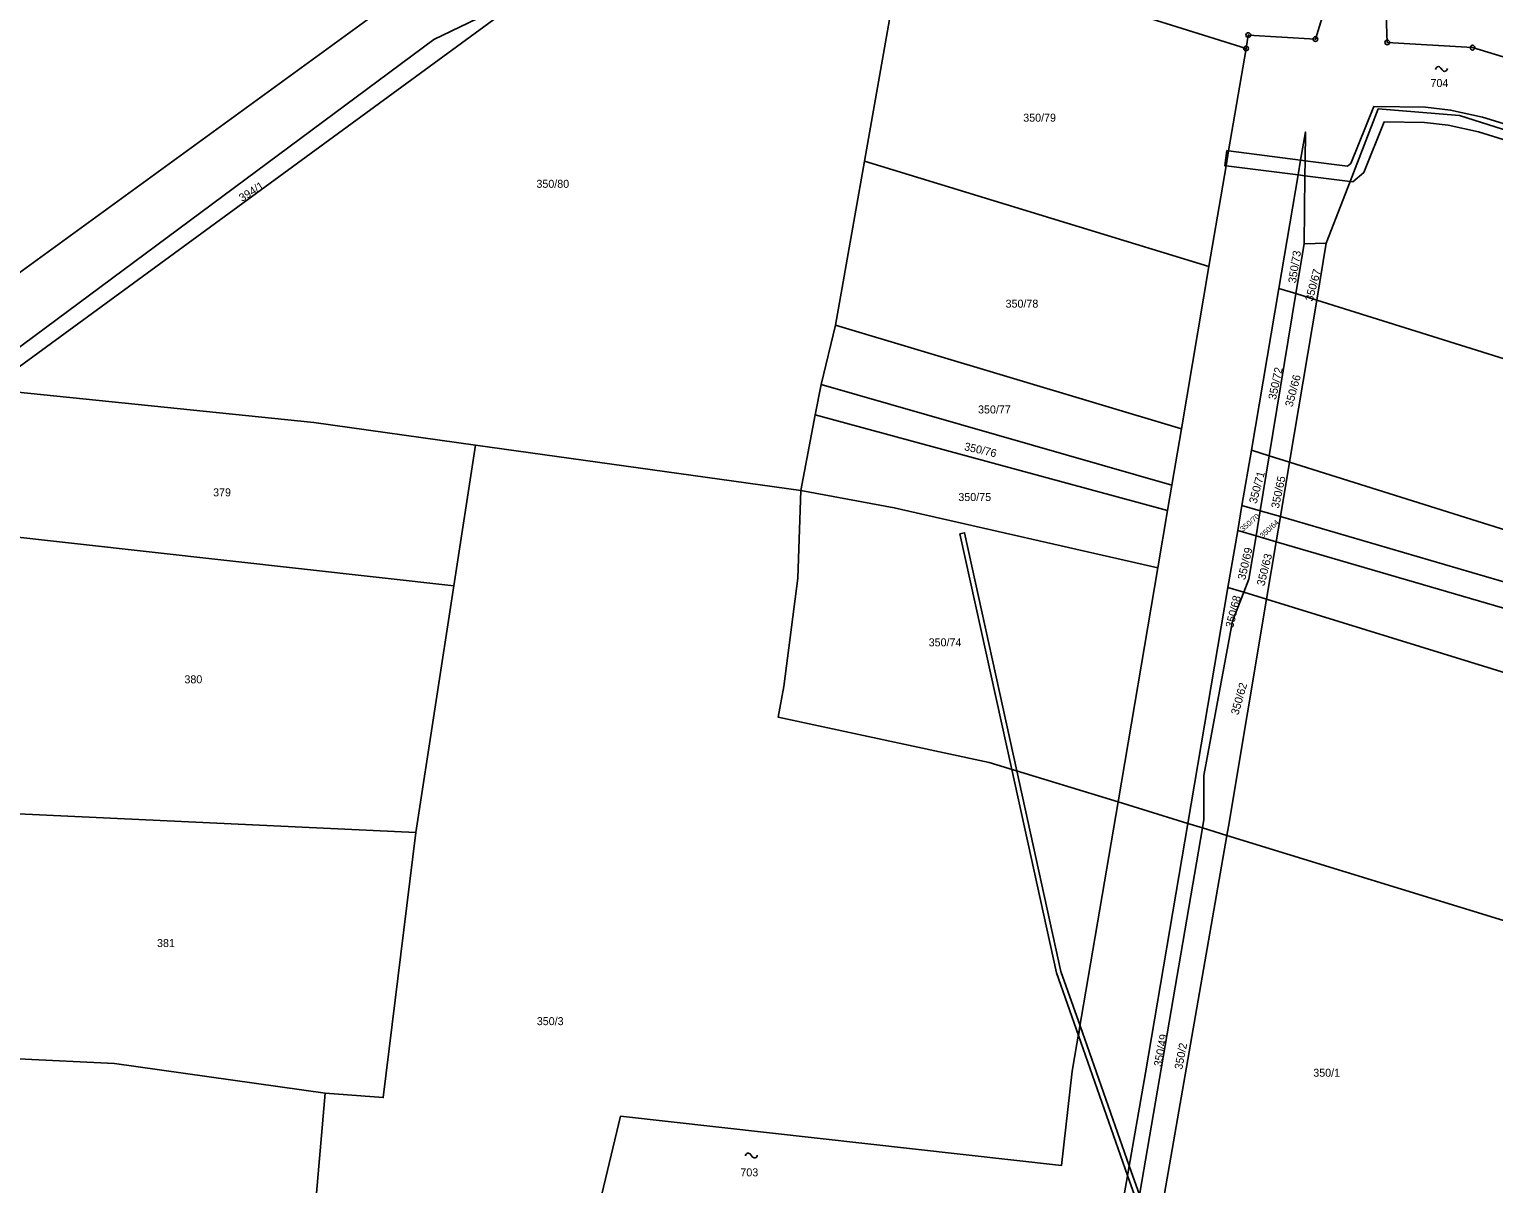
# Model space of a CAD drawing. Extents: x -758582 to -751794, y -998770 to -994350.
# Drawn here: x -756359.8 to -756048.6, y -995042.4 to -994797.3 of the extents above; entities that cross this region are included whole.
import ezdxf

# ---------------------------------------------------------------- set-up
doc = ezdxf.new("R2010")
doc.units = 0
for name, color, linetype in [('Hranice parcel', 7, 'Continuous'), ('Parcelní čísla', 7, 'Continuous'), ('Věcná břemena k části', 7, 'Continuous'), ('Značky bodu BP', 7, 'Continuous'), ('Značky budov', 7, 'Continuous')]:
    doc.layers.add(name, color=color, linetype=linetype)

msp = doc.modelspace()

# ---------------------------------------------------------------- linework, layer by layer
at = {"layer": 'Hranice parcel'}
for p, q in [((-756086.52, -994799.34), (-756077.42, -994769.66)), ((-756072.33, -994770.65), (-756071.25, -994800.04)), ((-756174.03, -994778.41), (-756182.33, -994825.28)), ((-756174.03, -994778.41), (-756101.26, -994801.32)), ((-756368.47, -994873.7), (-756253.61, -994789.69)), ((-756281.77, -994790.62), (-756367.18, -994852.8)), ((-756101.26, -994801.32), (-756100.77, -994798.48)), ((-756100.77, -994798.48), (-756086.52, -994799.34)), ((-756182.33, -994825.28), (-756188.49, -994860.1)), ((-756109.13, -994847.66), (-756182.33, -994825.28)), ((-756088.93, -994842.79), (-756090.67, -994853.4)), ((-756088.93, -994842.79), (-756084.22, -994842.66)), ((-756084.22, -994842.66), (-756086.25, -994854.78)), ((-756109.13, -994847.66), (-756114.98, -994882.08)), ((-756100.13, -994886.64), (-756094.29, -994852.27)), ((-756090.67, -994853.4), (-756094.29, -994852.27)), ((-756090.67, -994853.4), (-756096.32, -994887.83)), ((-756086.25, -994854.78), (-756092.02, -994889.17)), ((-756086.25, -994854.78), (-756090.67, -994853.4)), ((-755905.48, -994911.3), (-756086.25, -994854.78)), ((-756188.49, -994860.1), (-756191.49, -994872.7)), ((-756114.98, -994882.08), (-756188.49, -994860.1)), ((-756191.49, -994872.7), (-756192.81, -994879.15)), ((-756117.01, -994894.05), (-756191.49, -994872.7)), ((-756192.81, -994879.15), (-756195.86, -994895.23)), ((-756117.93, -994899.48), (-756192.81, -994879.15)), ((-756114.98, -994882.08), (-756117.01, -994894.05)), ((-756264.95, -994885.59), (-756269.57, -994915.48)), ((-756195.86, -994895.23), (-756264.95, -994885.59)), ((-756102.12, -994898.36), (-756100.13, -994886.64)), ((-756096.32, -994887.83), (-756100.13, -994886.64)), ((-756096.32, -994887.83), (-756098.24, -994899.49)), ((-756092.02, -994889.17), (-756096.32, -994887.83)), ((-756092.02, -994889.17), (-756093.96, -994900.74)), ((-756117.01, -994894.05), (-756117.93, -994899.48)), ((-756117.93, -994899.48), (-756120, -994911.65)), ((-756103.03, -994903.71), (-756102.12, -994898.36)), ((-756098.24, -994899.49), (-756102.12, -994898.36)), ((-756098.24, -994899.49), (-756099.12, -994904.85)), ((-756093.96, -994900.74), (-756098.24, -994899.49)), ((-756093.96, -994900.74), (-756094.86, -994906.09)), ((-755913.68, -994953.37), (-756093.96, -994900.74)), ((-756373.06, -994903.94), (-756269.57, -994915.48)), ((-756105.09, -994915.79), (-756103.03, -994903.71)), ((-756099.12, -994904.85), (-756103.03, -994903.71)), ((-756094.86, -994906.09), (-756099.12, -994904.85)), ((-756094.86, -994906.09), (-756096.9, -994918.28)), ((-755914.5, -994958.67), (-756094.86, -994906.09)), ((-756120, -994911.65), (-756128.44, -994961.35)), ((-756269.57, -994915.48), (-756277.66, -994967.84)), ((-756113.6, -994965.91), (-756105.09, -994915.79)), ((-756101.73, -994916.81), (-756105.09, -994915.79)), ((-756101.73, -994916.81), (-756104.15, -994922.93)), ((-756096.9, -994918.28), (-756101.73, -994916.81)), ((-756128.44, -994961.35), (-756113.6, -994965.91)), ((-756381.87, -994962.95), (-756277.66, -994967.84)), ((-756110.5, -994966.86), (-756125.92, -995056.48)), ((-756110.5, -994966.86), (-756113.6, -994965.91)), ((-756110.19, -994965.07), (-756110.5, -994966.86)), ((-756105.33, -994968.45), (-756110.5, -994966.86)), ((-756105.33, -994968.45), (-756120.81, -995057.12)), ((-756042.86, -994987.64), (-756105.33, -994968.45))]:
    msp.add_line(p, q, dxfattribs=at)
for points in [[(-756253.61, -994789.69), (-756273.78, -994799.42), (-756368.18, -994869.46)], [(-756071.25, -994800.04), (-756053.14, -994801.16), (-755892.22, -994850.06), (-755894.52, -994857.69)], [(-756101.26, -994801.32), (-756104.95, -994823.07), (-756105.49, -994826.28), (-756109.13, -994847.66)], [(-756084.22, -994842.66), (-756079.17, -994829.59), (-756073.22, -994814.18)], [(-756073.22, -994814.18), (-756055.93, -994815.59), (-755897.05, -994866.03)], [(-756094.29, -994852.27), (-756090.2, -994828.2), (-756089.67, -994825.06), (-756088.65, -994819.06), (-756088.72, -994825.18), (-756088.76, -994828.38), (-756088.93, -994842.79)], [(-756368.47, -994873.7), (-756299.29, -994880.74), (-756264.95, -994885.59)], [(-755912.3, -994944.36), (-756023.52, -994910.68), (-756092.02, -994889.17)], [(-756128.44, -994961.35), (-756155.83, -994952.96), (-756200.68, -994943.33), (-756199.43, -994936.86), (-756196.48, -994913.85), (-756195.86, -994895.23)], [(-756120, -994911.65), (-756175.98, -994898.88), (-756195.86, -994895.23)], [(-756099.12, -994904.85), (-756100.63, -994914.03), (-756101.73, -994916.81)], [(-756096.9, -994918.28), (-756105, -994966.58), (-756105.33, -994968.45)], [(-755916.67, -994973.02), (-755989.55, -994951.4), (-756096.9, -994918.28)], [(-756104.15, -994922.93), (-756110.2, -994955.75), (-756110.19, -994965.07)], [(-756234.17, -995028.1), (-756140.46, -995038.54), (-756138.16, -995018.51), (-756128.44, -994961.35)], [(-756277.66, -994967.84), (-756284.57, -995024.14), (-756296.89, -995023.16)], [(-756113.6, -994965.91), (-756122.6, -995018.87), (-756129.13, -995056.13)], [(-756362.08, -995015.86), (-756341.64, -995016.88), (-756296.89, -995023.16)], [(-756296.89, -995023.16), (-756301.28, -995073.82), (-756306.95, -995125.13), (-756317.06, -995199.97), (-756321.88, -995219.72)], [(-756295.79, -995218.6), (-756267.28, -995166.44), (-756234.17, -995028.1)]]:
    msp.add_lwpolyline(points, dxfattribs=at)
at = {"layer": 'Věcná břemena k části'}
for points in [[(-756088.72, -994825.18), (-756088.76, -994828.38), (-756079.17, -994829.59), (-756073.22, -994814.18), (-756055.93, -994815.59), (-755897.05, -994866.03), (-755893.83, -994867.05), (-755893.03, -994864.4), (-755896.29, -994863.5), (-755899.3, -994862.67), (-755925.08, -994855.31), (-755970.88, -994840.97), (-756016.69, -994826.72), (-756039.51, -994819.46), (-756051.05, -994815.89), (-756057.79, -994814.43), (-756063.16, -994813.8), (-756074.11, -994813.66), (-756078.96, -994825.73), (-756079.69, -994826.35)], [(-755893.95, -994867.51), (-755893.83, -994867.05), (-755897.05, -994866.03), (-756055.93, -994815.59), (-756073.22, -994814.18), (-756079.17, -994829.59), (-756078.6, -994829.66), (-756076.25, -994827.69), (-756071.94, -994816.93), (-756063.37, -994817.04), (-756058.32, -994817.63), (-756051.89, -994819.03), (-756040.48, -994822.55), (-756017.66, -994829.81), (-755971.85, -994844.06), (-755926.01, -994858.42), (-755900.18, -994865.79)], [(-756105.37, -994823.02), (-756105.78, -994826.24), (-756105.49, -994826.28), (-756104.95, -994823.07)], [(-756104.95, -994823.07), (-756105.49, -994826.28), (-756090.2, -994828.2), (-756089.67, -994825.06)], [(-756089.67, -994825.06), (-756090.2, -994828.2), (-756088.76, -994828.38), (-756088.72, -994825.18)], [(-756149.94, -994954.76), (-756161.06, -994904.19), (-756162.04, -994904.41), (-756151.04, -994954.43)], [(-756151.04, -994954.43), (-756141.54, -994997.65), (-756136.87, -995010.93), (-756136.53, -995008.9), (-756140.58, -994997.37), (-756149.94, -994954.76)], [(-756136.53, -995008.9), (-756136.87, -995010.93), (-756126.42, -995040.65), (-756126.07, -995038.64)], [(-756126.42, -995040.65), (-756124.26, -995046.8), (-756120.81, -995057.12), (-756119.5, -995057.3), (-756120.4, -995054.76), (-756123.91, -995044.78), (-756126.07, -995038.64)]]:
    msp.add_lwpolyline(points, close=True, dxfattribs=at)
at = {"layer": 'Značky bodu BP'}
for centre, radius in [((-756100.77, -994798.48), 0.5), ((-756100.77, -994798.48), 0.0303), ((-756086.52, -994799.34), 0.5), ((-756086.52, -994799.34), 0.0303), ((-756071.25, -994800.04), 0.5), ((-756071.25, -994800.04), 0.0303), ((-756101.26, -994801.32), 0.5), ((-756101.26, -994801.32), 0.0303), ((-756053.14, -994801.16), 0.5), ((-756053.14, -994801.16), 0.0303)]:
    msp.add_circle(centre, radius, dxfattribs=at)
at = {"layer": 'Značky budov'}
for p, q in [((-756059.89, -994805.49), (-756059.59, -994805.89)), ((-756206.5, -995036.22), (-756206.2, -995036.62))]:
    msp.add_line(p, q, dxfattribs=at)
for centre, start, end in [((-756060.4, -994805.78), 29.2914, 181.2189), ((-756059.08, -994805.6), 209.2914, 1.2189), ((-756207.01, -995036.51), 29.2914, 181.2189), ((-756205.69, -995036.33), 209.2914, 1.2189)]:
    msp.add_arc(centre, 0.588, start, end, dxfattribs=at)

# ---------------------------------------------------------------- texts
at = {"layer": 'Parcelní čísla'}
for s, p in [('704', (-756062.07, -994809.52)), ('350/79', (-756148.59, -994816.88)), ('350/80', (-756252.01, -994830.92)), ('350/78', (-756152.34, -994856.37)), ('350/77', (-756158.19, -994878.84)), ('379', (-756320.7, -994896.45)), ('350/75', (-756162.37, -994897.44)), ('350/74', (-756168.68, -994928.3)), ('380', (-756326.79, -994936.15)), ('381', (-756332.61, -994992.16)), ('350/3', (-756251.93, -995008.74)), ('350/1', (-756086.97, -995019.7)), ('703', (-756208.68, -995040.85))]:
    msp.add_text(s, height=1.7, dxfattribs=at).set_placement(p)
for s, height, rotation, p in [('394/1', 1.7, 32, (-756314.54, -994833.95)), ('350/73', 1.7, 81, (-756090.66, -994851.27)), ('350/67', 1.7, 75, (-756087.11, -994855.16)), ('350/72', 1.7, 78, (-756094.91, -994876.04)), ('350/66', 1.7, 75, (-756091.39, -994877.58)), ('350/76', 1.7, 347, (-756161.25, -994886.61)), ('350/71', 1.7, 75, (-756099.03, -994898.11)), ('350/65', 1.7, 78, (-756094.3, -994899.13)), ('350/70', 1.14, 41, (-756101.9, -994904.01)), ('350/64', 1.14, 43, (-756097.68, -994905.41)), ('350/69', 1.7, 77, (-756101.43, -994914.3)), ('350/63', 1.7, 76, (-756097.37, -994915.58)), ('350/68', 1.7, 76, (-756104.01, -994924.5)), ('350/62', 1.7, 74, (-756102.9, -994942.99)), ('350/49', 1.7, 79, (-756119.22, -995017.68)), ('350/2', 1.7, 79, (-756114.83, -995018.27))]:
    msp.add_text(s, height=height, rotation=rotation, dxfattribs=at).set_placement(p)

doc.saveas('drawing.dxf')
